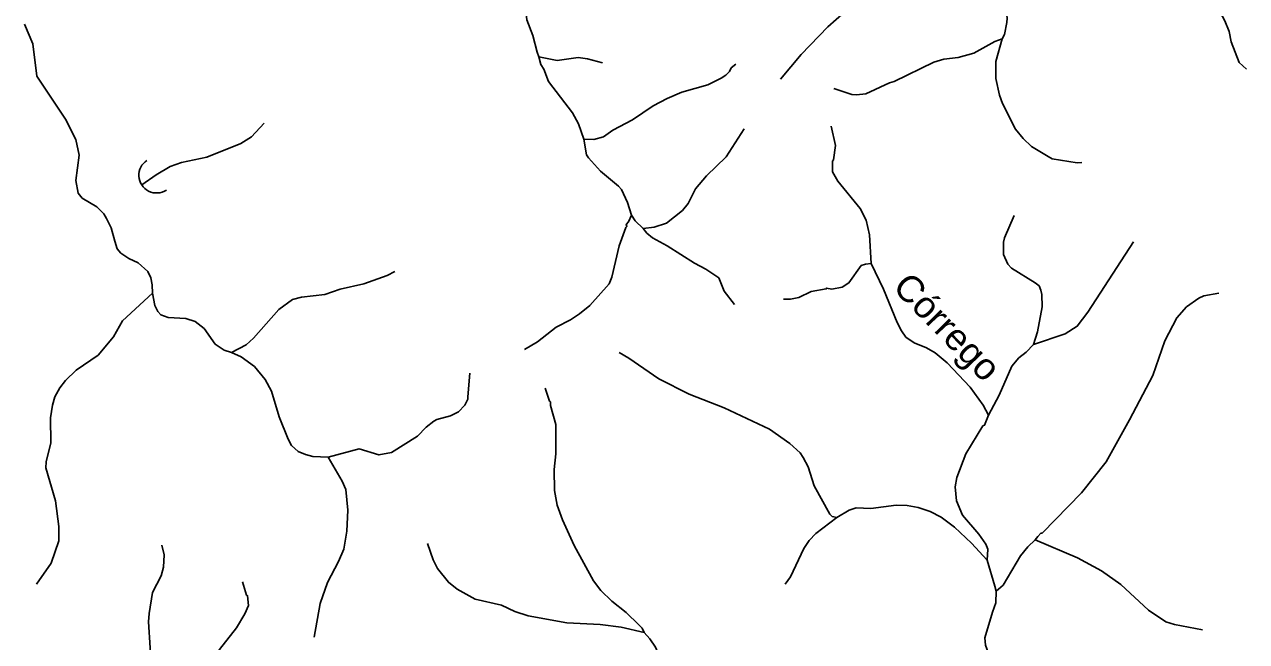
# Model space of a CAD drawing. Extents: x 346.5 to 372.4, y 7400.3 to 7428.2.
# Drawn here: x 354.853 to 358.577, y 7404.832 to 7406.713 of the extents above; entities that cross this region are included whole.
import ezdxf
from ezdxf.enums import TextEntityAlignment as Align

# ---------------------------------------------------------------- set-up
doc = ezdxf.new("R2010")
doc.units = 0
doc.header["$LTSCALE"] = 0.032
doc.layers.add('11', color=7, linetype='Continuous', lineweight=25)
doc.layers.add('7', color=7, linetype='Continuous', lineweight=25)
doc.layers.add('61', color=7, linetype='Continuous')

msp = doc.modelspace()

# ---------------------------------------------------------------- linework, layer by layer
at = {"layer": '11'}
msp.add_arc((355.2557, 7406.2534), 0.0541, 122.8675, 303.5705, dxfattribs=at)
at = {"layer": '7'}
for points in [[(356.3134, 7407.0341), (356.324, 7407.0076), (356.3418, 7406.9758), (356.3458, 7406.9615), (356.3482, 7406.9184), (356.3713, 7406.8324), (356.3841, 7406.7272), (356.4024, 7406.6794), (356.4155, 7406.6286), (356.4203, 7406.6148)], [(357.6107, 7407.0517), (357.6049, 7407.0322), (357.5962, 7407.0172), (357.5317, 7406.9487), (357.5189, 7406.9256), (357.5014, 7406.8818), (357.4846, 7406.8571), (357.4321, 7406.8108), (357.3771, 7406.7726), (357.3006, 7406.7056), (357.2193, 7406.6212), (357.1563, 7406.5463)], [(358.5765, 7406.5765), (358.5541, 7406.5973), (358.5294, 7406.6602), (358.5231, 7406.6921), (358.5103, 7406.724), (358.4697, 7406.8005), (358.4466, 7406.8292), (358.4051, 7406.8658), (358.3764, 7406.8849), (358.3462, 7406.8985), (358.2824, 7406.9136), (358.2346, 7406.9192), (358.1549, 7406.916), (358.123, 7406.912), (358.0497, 7406.8913), (358.0067, 7406.8826), (357.9174, 7406.8523), (357.8744, 7406.8467), (357.7933, 7406.8513)], [(357.8316, 7406.6697), (357.8391, 7406.6828), (357.8457, 7406.7192), (357.8473, 7406.732), (357.8441, 7406.7575), (357.8361, 7406.783), (357.8114, 7406.8268), (357.7933, 7406.8513)], [(354.8531, 7406.7144), (354.8786, 7406.6539), (354.8906, 7406.555), (354.9782, 7406.4243), (355.0093, 7406.3622), (355.0197, 7406.3144), (355.0101, 7406.2378), (355.0165, 7406.1988), (355.0293, 7406.1836), (355.0739, 7406.1574), (355.0946, 7406.1358), (355.1034, 7406.1215), (355.1169, 7406.0928), (355.1281, 7406.0521), (355.1352, 7406.029), (355.1472, 7406.0155), (355.1711, 7405.9995), (355.1998, 7405.9868), (355.2293, 7405.9597), (355.238, 7405.9406), (355.2426, 7405.9192), (355.2433, 7405.8944)], [(357.8316, 7406.6697), (357.8098, 7406.661), (357.7453, 7406.6251), (357.6974, 7406.6124), (357.6544, 7406.6076), (357.6241, 7406.598), (357.503, 7406.5391), (357.4886, 7406.5351), (357.4169, 7406.5016), (357.3882, 7406.4984), (357.3739, 7406.5), (357.3189, 7406.5184)], [(358.0744, 7406.292), (358.0608, 7406.2912), (358.0098, 7406.2992), (357.9843, 7406.304), (357.9716, 7406.3104), (357.9214, 7406.3414), (357.8959, 7406.3654), (357.8728, 7406.394), (357.8329, 7406.4721), (357.8241, 7406.4977), (357.813, 7406.5487), (357.813, 7406.5997), (357.8316, 7406.6697)], [(356.4203, 7406.6148), (356.4265, 7406.5907), (356.4351, 7406.5773), (356.4494, 7406.5391), (356.5227, 7406.4435), (356.5411, 7406.41), (356.557, 7406.3635)], [(356.6144, 7406.5965), (356.569, 7406.6084), (356.5403, 7406.6124), (356.4765, 7406.6036), (356.4203, 7406.6148)], [(357.0208, 7406.5925), (357.0065, 7406.5805), (357.0009, 7406.5694), (356.9898, 7406.5582), (356.9762, 7406.5494), (356.9356, 7406.5295), (356.8559, 7406.5072), (356.8112, 7406.4873), (356.7682, 7406.465), (356.706, 7406.4227), (356.6455, 7406.3908), (356.6168, 7406.3701), (356.5881, 7406.3622), (356.557, 7406.3635)], [(355.5831, 7406.4124), (355.5449, 7406.3709), (355.5122, 7406.3502), (355.4086, 7406.3088), (355.3321, 7406.2928), (355.297, 7406.2801), (355.2548, 7406.2546), (355.2104, 7406.2238)], [(357.3109, 7406.4028), (357.3237, 7406.3446), (357.3181, 7406.3), (357.3149, 7406.296), (357.3149, 7406.2641), (357.3308, 7406.2354), (357.3994, 7406.1518), (357.4177, 7406.1167), (357.4281, 7406.0721), (357.4323, 7405.9843)], [(357.0463, 7406.3948), (356.9913, 7406.3096), (356.9308, 7406.2522), (356.8973, 7406.2123), (356.875, 7406.1677), (356.8582, 7406.1462), (356.8088, 7406.1079), (356.7714, 7406.0952), (356.7381, 7406.0916)], [(356.557, 7406.3635), (356.5658, 7406.3159), (356.5713, 7406.3064), (356.608, 7406.2657), (356.663, 7406.2203), (356.6718, 7406.2099), (356.6901, 7406.1709), (356.7023, 7406.1319)], [(356.7023, 7406.1319), (356.6934, 7406.1112), (356.6865, 7406.1029), (356.6885, 7406.0968), (356.6853, 7406.0944), (356.6646, 7406.0386), (356.6423, 7405.943), (356.6343, 7405.923), (356.5753, 7405.8561), (356.5443, 7405.8314), (356.5164, 7405.8131), (356.4733, 7405.7907), (356.416, 7405.7461), (356.3769, 7405.7222)], [(356.7023, 7406.1319), (356.7134, 7406.1143), (356.7381, 7406.0916)], [(357.868, 7406.1303), (357.8393, 7406.0625), (357.8361, 7406.0498), (357.8361, 7406.0115), (357.8488, 7405.9828), (357.86, 7405.9701), (357.9325, 7405.9254), (357.9445, 7405.9159), (357.9501, 7405.9031), (357.9532, 7405.8904), (357.9533, 7405.8521), (357.9397, 7405.7764), (357.927, 7405.7373)], [(356.7381, 7406.0916), (356.7491, 7406.0771), (356.7666, 7406.0625), (356.8112, 7406.0386), (356.8949, 7405.9852), (356.9292, 7405.9677), (356.9682, 7405.9406), (356.985, 7405.8999), (357.0161, 7405.8593)], [(358.2322, 7406.0506), (358.0927, 7405.8362), (358.0608, 7405.7931), (358.0242, 7405.77), (357.927, 7405.7373)], [(355.4838, 7405.7135), (355.5282, 7405.7365), (355.5505, 7405.7565), (355.6286, 7405.8441), (355.67, 7405.8744), (355.6971, 7405.8816), (355.7688, 7405.8896), (355.8151, 7405.9063), (355.8868, 7405.9222), (355.9585, 7405.9477), (355.9816, 7405.9597)], [(357.4323, 7405.9843), (357.4153, 7405.9828), (357.4026, 7405.978), (357.3651, 7405.9254), (357.3444, 7405.9119), (357.3133, 7405.9063), (357.2966, 7405.9095), (357.2958, 7405.9071), (357.2496, 7405.8991), (357.2129, 7405.8808), (357.1874, 7405.876), (357.1659, 7405.876)], [(357.4323, 7405.9843), (357.4703, 7405.9063), (357.5125, 7405.8043), (357.5253, 7405.7788), (357.5388, 7405.7604), (357.5636, 7405.7429), (357.6018, 7405.727), (357.6273, 7405.7126), (357.664, 7405.6816), (357.7341, 7405.6075), (357.7739, 7405.5525), (357.7899, 7405.5219)], [(355.2433, 7405.8944), (355.152, 7405.8099), (355.1241, 7405.7613), (355.0779, 7405.7055), (355.0109, 7405.6592), (354.9783, 7405.6274), (354.9607, 7405.6059), (354.9456, 7405.578), (354.9384, 7405.5525), (354.9328, 7405.5142), (354.9336, 7405.4377), (354.9193, 7405.3803), (354.9185, 7405.3612), (354.948, 7405.2608), (354.9575, 7405.1827), (354.9575, 7405.1389), (354.9344, 7405.0711), (354.8898, 7405.0066)], [(355.2433, 7405.8944), (355.25, 7405.8561), (355.2596, 7405.8378), (355.2691, 7405.8282), (355.2907, 7405.8202), (355.3449, 7405.817), (355.3735, 7405.8075), (355.4006, 7405.7868), (355.4341, 7405.739), (355.4612, 7405.7198), (355.4838, 7405.7135)], [(358.492, 7405.8936), (358.4466, 7405.8864), (358.4306, 7405.8792), (358.394, 7405.8521), (358.3645, 7405.8187), (358.3278, 7405.7485), (358.2912, 7405.6433), (358.2202, 7405.5078), (358.1485, 7405.3795), (358.0736, 7405.2855), (357.9541, 7405.1627), (357.9502, 7405.1627), (357.9402, 7405.1527), (357.9326, 7405.1417)], [(357.927, 7405.7373), (357.9046, 7405.7142), (357.8823, 7405.6967), (357.8616, 7405.672), (357.8225, 7405.5836), (357.7899, 7405.5219)], [(355.4838, 7405.7135), (355.513, 7405.6999), (355.5544, 7405.6704), (355.5863, 7405.6306), (355.6054, 7405.5955), (355.6294, 7405.5174), (355.6564, 7405.4489), (355.6668, 7405.4297), (355.6875, 7405.4114), (355.7099, 7405.4018), (355.7322, 7405.3963), (355.7786, 7405.3937)], [(356.6654, 7405.7127), (356.6949, 7405.6959), (356.7857, 7405.6329), (356.8782, 7405.5859), (356.985, 7405.5445), (357.1228, 7405.4799), (357.185, 7405.4361), (357.2161, 7405.4074), (357.2256, 7405.3931), (357.2408, 7405.3644), (357.2591, 7405.307), (357.3065, 7405.2199), (357.3141, 7405.213), (357.3278, 7405.2103)], [(355.7786, 7405.3937), (355.8732, 7405.4194), (355.933, 7405.401), (355.9713, 7405.4082), (356.0509, 7405.4584), (356.0772, 7405.4855), (356.1004, 7405.5038), (356.1099, 7405.5094), (356.1514, 7405.5206), (356.1753, 7405.5325), (356.1952, 7405.5525), (356.204, 7405.5708), (356.204, 7405.578), (356.2103, 7405.6505)], [(356.4391, 7405.6043), (356.4526, 7405.5652), (356.4558, 7405.5628), (356.4558, 7405.5517), (356.4717, 7405.4935), (356.4717, 7405.4042), (356.4669, 7405.3564), (356.4685, 7405.2927), (356.4757, 7405.248), (356.4924, 7405.2034), (356.5283, 7405.1253), (356.5865, 7405.0169), (356.6096, 7404.9874), (356.6431, 7404.9548), (356.6861, 7404.9205), (356.7252, 7404.883), (356.7352, 7404.8725), (356.7407, 7404.8594)], [(357.7899, 7405.5219), (357.7782, 7405.4918), (357.7731, 7405.4895), (357.7213, 7405.4042), (357.6934, 7405.3325), (357.6887, 7405.3038), (357.6926, 7405.2608), (357.711, 7405.2178), (357.7604, 7405.1596), (357.7819, 7405.1285), (357.7883, 7405.1133), (357.7858, 7405.0799)], [(355.7786, 7405.3937), (355.8214, 7405.3214), (355.8326, 7405.2959), (355.8382, 7405.2321), (355.835, 7405.1683), (355.8262, 7405.1142), (355.8103, 7405.0759), (355.776, 7405.0121), (355.7545, 7404.9484), (355.7354, 7404.8456)], [(357.3278, 7405.2103), (357.3659, 7405.2321), (357.3866, 7405.2393), (357.4313, 7405.2377), (357.5094, 7405.248), (357.5428, 7405.2464), (357.5763, 7405.2409), (357.613, 7405.2281), (357.6456, 7405.2114), (357.6863, 7405.1811), (357.7381, 7405.1317), (357.7858, 7405.0799)], [(357.3278, 7405.2103), (357.2647, 7405.1612), (357.244, 7405.1404), (357.2272, 7405.1157), (357.1874, 7405.0297), (357.1707, 7405.0066)], [(357.9326, 7405.1417), (357.9102, 7405.1213), (357.8879, 7405.0934), (357.8353, 7405.0042), (357.8134, 7404.9854)], [(357.9326, 7405.1417), (358.0616, 7405.0878), (358.1342, 7405.048), (358.1931, 7405.0058), (358.2776, 7404.9276), (358.3302, 7404.8918), (358.3573, 7404.8838), (358.4426, 7404.8679)], [(355.2715, 7405.1261), (355.2787, 7405.0966), (355.2771, 7405.0584), (355.2699, 7405.0329), (355.2436, 7404.9819), (355.2333, 7404.9181), (355.2309, 7404.8926), (355.2365, 7404.8129), (355.2349, 7404.7874), (355.2237, 7404.7619), (355.1639, 7404.6854), (355.1456, 7404.644), (355.1408, 7404.6185), (355.1408, 7404.5802), (355.1472, 7404.5292), (355.146, 7404.4999)], [(356.0812, 7405.1309), (356.098, 7405.0807), (356.1115, 7405.0552), (356.145, 7405.0129), (356.1713, 7404.9914), (356.2263, 7404.9611), (356.3068, 7404.9428), (356.3474, 7404.9237), (356.3873, 7404.9109), (356.5052, 7404.8894), (356.6072, 7404.8838), (356.671, 7404.8759), (356.7407, 7404.8594)], [(357.7858, 7405.0799), (357.8093, 7405.0005), (357.8134, 7404.9854)], [(355.517, 7405.0145), (355.5297, 7404.9739), (355.5329, 7404.9715), (355.5361, 7404.942), (355.525, 7404.9165), (355.4987, 7404.8743), (355.4476, 7404.8081), (355.4317, 7404.7826), (355.407, 7404.6925), (355.3895, 7404.6615), (355.3608, 7404.6264), (355.3385, 7404.6089), (355.3034, 7404.5889), (355.2524, 7404.5738), (355.2158, 7404.5563), (355.146, 7404.4999)], [(357.8134, 7404.9854), (357.8122, 7404.95), (357.8026, 7404.9213), (357.7787, 7404.8432), (357.7811, 7404.8209), (357.7891, 7404.7986), (357.8143, 7404.748)], [(356.7407, 7404.8594), (356.7586, 7404.8408), (356.7762, 7404.8145), (356.8104, 7404.7348), (356.8383, 7404.687), (356.8567, 7404.667), (356.8961, 7404.6474)]]:
    msp.add_lwpolyline(points, dxfattribs=at)

# ---------------------------------------------------------------- texts
at = {"layer": '61', "width": 1.05}
msp.add_text('Córrego', height=0.08, rotation=314.29, dxfattribs=at).set_placement((357.6362, 7405.7637), align=Align.CENTER)

doc.saveas('drawing.dxf')
